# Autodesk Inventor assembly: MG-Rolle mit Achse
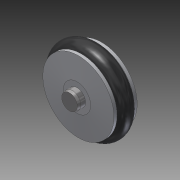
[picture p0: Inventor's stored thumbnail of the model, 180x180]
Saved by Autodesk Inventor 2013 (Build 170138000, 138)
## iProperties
Created: 2012-07
Part Number: MG-Rolle mit Achse
Document SubType Name: Assembly
Designer: rYan
Mass: 0.935051 g
Surface Area: 6.45272 cm^2
Volume: 0.368723 cm^3
Density: 2.53592 g/cm^3
Author: rYan
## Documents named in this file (4)
- D:\SVN\2013\Inventor\Antrieb\MG-Rolle mit Achse.iam
- D:\SVN\2013\Inventor\Antrieb\Rolle.ipt
- D:\SVN\2013\Inventor\Antrieb\O-Ring 7x2.5.ipt
- D:\SVN\2013\Inventor\Inhaltscenter\en-US\ISO 2338(1)\ISO 2338 - 2,5 m6 x 6DIN EN.ipt
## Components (3 placed, 3 different names)
1. Rolle:1 — Passend:1, Tangential:1
2. DIN EN ISO 2338 2,5 m6 x 6:1
3. O-Ring 7x2.5:1 — Passend:1, Tangential:1
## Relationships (2: Mate 1, Tangent 1)
- Passend:1 [Mate]: Rolle:1 ↔ O-Ring 7x2.5:1
- Tangential:1: Rolle:1 ↔ O-Ring 7x2.5:1
